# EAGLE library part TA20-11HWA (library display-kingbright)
50mm (2.0 INCH) 5x7 DOT MATRIX DISPLAY Source: http://www.kingbright.com/manager/upload/pdf/TC20-11EWA(Ver1189410378.9)
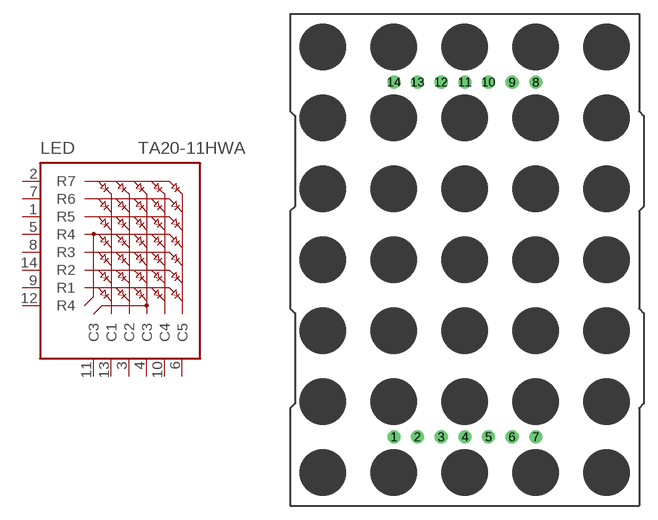
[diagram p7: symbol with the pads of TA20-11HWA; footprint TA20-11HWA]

Designator prefix LED

## TA20-11HWA (OC_FARNELL: unknown; OC_NEWARK: unknown)  [TA20-11HWA]
1  R5  pas
2  R7  pas
3  C2  pas
4  C3  pas
5  R4  pas
6  C5  pas
7  R6  pas
8  R3  pas
9  R1  pas
10  C4  pas
11  C3  pas
12  R4  pas
13  C1  pas
14  R2  pas

## Footprint TA20-11HWA (pad centres in mm)
50mm (2.0 INCH) 5x7 DOT MATRIX DISPLAY Source: http://www.kingbright.com/manager/upload/pdf/TC20-11EWA(Ver1189410378.9)
drill 0.9 pad 1.4 round: 1 -7.62,-19.05; 2 -5.08,-19.05; 3 -2.54,-19.05; 4 0,-19.05; 5 2.54,-19.05; 6 5.08,-19.05; 7 7.62,-19.05; 8 7.62,19.05; 9 5.08,19.05; 10 2.54,19.05; 11 0,19.05; 12 -2.54,19.05; 13 -5.08,19.05; 14 -7.62,19.05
